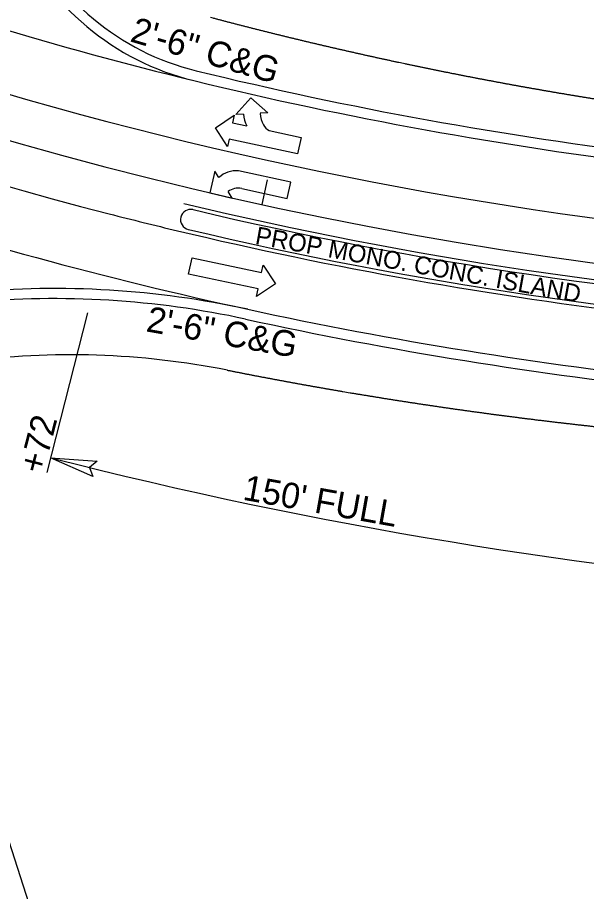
# Model space of a CAD drawing. Extents: x 1616561 to 1622460, y 896726 to 899651.
# Drawn here: x 1619580.2 to 1619692.2, y 897924.5 to 898096.6 of the extents above; entities that cross this region are included whole.
import ezdxf

# ---------------------------------------------------------------- set-up
doc = ezdxf.new("R2010")
doc.units = 0
for name, color, linetype in [('Exist Boundary Study Area', 7, 'Continuous'), ('Old_Level_3', 7, 'Continuous'), ('Prop Dimension', 7, 'Continuous'), ('Prop Guardrail', 7, 'Continuous'), ('Prop Horizontal Alignment Tick Small', 7, 'Continuous'), ('Prop Lane Arrow CELL', 7, 'Continuous'), ('Prop Shade Medium', 7, 'Continuous'), ('Prop Superelevation  Arrow CELL', 7, 'Continuous'), ('Prop Terminator CELL', 7, 'Continuous'), ('Sheet Cutting Line CELL', 7, 'Continuous'), ('Sheet North Arrow CELL', 7, 'Continuous')]:
    doc.layers.add(name, color=color, linetype=linetype)

msp = doc.modelspace()

# ---------------------------------------------------------------- linework, layer by layer
at = {"layer": 'Exist Boundary Study Area'}
for centre, radius, start, end in [((1619614.26, 898056.82), 2, 76.7118, 166.5693), ((1619799.51, 898841.24), 804, 256.71253, 266.38119), ((1619614.26, 898056.82), 2, 166.5693, 256.7115), ((1619799.51, 898841.24), 808, 256.71253, 266.33407)]:
    msp.add_arc(centre, radius, start, end, dxfattribs=at)
at = {"layer": 'Old_Level_3'}
for radius, start, end in [(808.75, 229.34838, 255.58792), (779.25, 244.13867, 256.29422), (791.25, 245.11013, 270), (820.75, 245.81358, 257.75937), (803.25, 256.56929, 266.38119), (808.75, 255.58792, 256.56929), (808.75, 256.56929, 270)]:
    msp.add_arc((1619799.51, 898841.24), radius, start, end, dxfattribs=at)
at = {"layer": 'Prop Dimension'}
msp.add_line((1619593.97, 898038.46), (1619585.91, 898007.01), dxfattribs=at)
msp.add_arc((1619814.99, 898901.46), 920.33, 255.63483, 265.65625, dxfattribs=at)
at = {"layer": 'Prop Guardrail'}
msp.add_arc((1619590.52, 897870.95), 159.23, 78.786, 97.4583, dxfattribs=at)
for points in [[(1619656.5, 898087.47), (1619655.24, 898087.74), (1619654.6, 898087.88), (1619653.97, 898088.01), (1619653.34, 898088.15), (1619652.7, 898088.29), (1619652.07, 898088.42), (1619651.44, 898088.56), (1619650.8, 898088.7), (1619650.17, 898088.84), (1619649.54, 898088.98), (1619648.9, 898089.12), (1619648.27, 898089.26), (1619647.64, 898089.4), (1619647.01, 898089.54), (1619646.37, 898089.69), (1619645.74, 898089.83), (1619645.11, 898089.97), (1619644.48, 898090.12), (1619643.85, 898090.26), (1619643.22, 898090.41), (1619642.58, 898090.55), (1619641.95, 898090.7), (1619641.32, 898090.84), (1619640.69, 898090.99), (1619640.06, 898091.14), (1619639.43, 898091.29), (1619638.8, 898091.44), (1619638.17, 898091.58), (1619637.54, 898091.73), (1619636.91, 898091.88), (1619636.28, 898092.04), (1619635.65, 898092.19), (1619635.02, 898092.34), (1619634.39, 898092.49), (1619633.76, 898092.64), (1619633.13, 898092.8), (1619632.5, 898092.95), (1619631.87, 898093.11), (1619631.24, 898093.26), (1619630.62, 898093.42), (1619629.99, 898093.57), (1619629.36, 898093.73), (1619628.73, 898093.89), (1619628.1, 898094.04), (1619627.47, 898094.2), (1619626.85, 898094.36), (1619626.22, 898094.52), (1619625.59, 898094.68), (1619624.96, 898094.84), (1619624.34, 898095), (1619623.71, 898095.16), (1619623.08, 898095.32), (1619622.46, 898095.49), (1619621.83, 898095.65), (1619621.2, 898095.81), (1619620.58, 898095.98), (1619619.95, 898096.14), (1619619.32, 898096.31), (1619618.7, 898096.47), (1619618.14, 898096.62)], [(1619703.74, 898079.02), (1619702.45, 898079.21), (1619701.81, 898079.31), (1619701.17, 898079.4), (1619700.53, 898079.5), (1619699.89, 898079.6), (1619699.25, 898079.69), (1619698.6, 898079.79), (1619697.96, 898079.89), (1619697.32, 898079.99), (1619696.68, 898080.09), (1619696.04, 898080.19), (1619695.4, 898080.29), (1619694.76, 898080.39), (1619694.12, 898080.5), (1619693.48, 898080.6), (1619692.84, 898080.7), (1619692.2, 898080.81), (1619691.56, 898080.91), (1619690.92, 898081.01), (1619690.28, 898081.12), (1619689.64, 898081.23), (1619689, 898081.33), (1619688.36, 898081.44), (1619687.72, 898081.55), (1619687.08, 898081.65), (1619686.44, 898081.76), (1619685.8, 898081.87), (1619685.16, 898081.98), (1619684.52, 898082.09), (1619683.88, 898082.2), (1619683.24, 898082.31), (1619682.6, 898082.43), (1619681.96, 898082.54), (1619681.32, 898082.65), (1619680.69, 898082.76), (1619680.05, 898082.88), (1619679.41, 898082.99), (1619678.77, 898083.11), (1619678.13, 898083.22), (1619677.49, 898083.34), (1619676.86, 898083.46), (1619676.22, 898083.57), (1619675.58, 898083.69), (1619674.94, 898083.81), (1619674.31, 898083.93), (1619673.67, 898084.05), (1619673.03, 898084.17), (1619672.39, 898084.29), (1619671.76, 898084.41), (1619671.12, 898084.53), (1619670.48, 898084.65), (1619669.85, 898084.78), (1619669.21, 898084.9), (1619668.57, 898085.02), (1619667.94, 898085.15), (1619667.3, 898085.27), (1619666.67, 898085.4), (1619666.03, 898085.52), (1619665.39, 898085.65), (1619664.76, 898085.78), (1619664.12, 898085.9), (1619663.49, 898086.03), (1619662.85, 898086.16), (1619662.22, 898086.29), (1619661.58, 898086.42), (1619660.95, 898086.55), (1619660.31, 898086.68), (1619659.68, 898086.81), (1619659.04, 898086.94), (1619658.41, 898087.07), (1619657.77, 898087.21), (1619657.14, 898087.34), (1619656.5, 898087.47)], [(1619621.48, 898027.14), (1619622.1, 898027.02), (1619622.41, 898026.96), (1619622.71, 898026.9), (1619623.02, 898026.84), (1619623.33, 898026.78), (1619623.63, 898026.72), (1619623.94, 898026.66), (1619624.25, 898026.6), (1619624.56, 898026.54), (1619624.86, 898026.48), (1619625.17, 898026.42), (1619625.48, 898026.36), (1619625.78, 898026.3), (1619626.09, 898026.24), (1619626.4, 898026.18), (1619626.71, 898026.12), (1619627.01, 898026.06), (1619627.32, 898026), (1619627.63, 898025.94), (1619627.94, 898025.89), (1619628.24, 898025.83), (1619628.55, 898025.77), (1619628.86, 898025.71), (1619629.17, 898025.65), (1619629.47, 898025.59), (1619629.78, 898025.54), (1619630.09, 898025.48), (1619630.4, 898025.42), (1619630.71, 898025.36), (1619631.01, 898025.31), (1619631.32, 898025.25), (1619631.63, 898025.19), (1619631.94, 898025.13), (1619632.24, 898025.08), (1619632.55, 898025.02), (1619632.86, 898024.96), (1619633.17, 898024.91), (1619633.48, 898024.85), (1619633.78, 898024.79), (1619634.09, 898024.74), (1619634.4, 898024.68), (1619634.71, 898024.62), (1619635.01, 898024.57), (1619635.32, 898024.51), (1619635.63, 898024.46), (1619635.94, 898024.4), (1619636.25, 898024.35), (1619636.55, 898024.29), (1619636.86, 898024.24), (1619637.17, 898024.18), (1619637.48, 898024.13), (1619637.79, 898024.07), (1619638.09, 898024.02), (1619638.4, 898023.96), (1619638.71, 898023.91), (1619639.02, 898023.85), (1619639.33, 898023.8), (1619639.64, 898023.74), (1619639.94, 898023.69), (1619640.25, 898023.64), (1619640.56, 898023.58), (1619640.87, 898023.53), (1619641.18, 898023.47), (1619641.49, 898023.42), (1619641.79, 898023.37), (1619642.1, 898023.31), (1619642.41, 898023.26), (1619642.72, 898023.21), (1619643.03, 898023.15), (1619643.34, 898023.1), (1619643.64, 898023.05), (1619643.95, 898023), (1619644.26, 898022.94)], [(1619644.26, 898022.94), (1619645.65, 898022.71), (1619646.34, 898022.59), (1619647.04, 898022.48), (1619647.73, 898022.36), (1619648.42, 898022.25), (1619649.12, 898022.13), (1619649.81, 898022.02), (1619650.51, 898021.91), (1619651.2, 898021.8), (1619651.9, 898021.68), (1619652.59, 898021.57), (1619653.29, 898021.46), (1619653.98, 898021.35), (1619654.68, 898021.24), (1619655.37, 898021.13), (1619656.07, 898021.03), (1619656.76, 898020.92), (1619657.46, 898020.81), (1619658.15, 898020.71), (1619658.85, 898020.6), (1619659.54, 898020.49), (1619660.24, 898020.39), (1619660.93, 898020.29), (1619661.63, 898020.18), (1619662.32, 898020.08), (1619663.02, 898019.98), (1619663.72, 898019.88), (1619664.41, 898019.77), (1619665.11, 898019.67), (1619665.8, 898019.57), (1619666.5, 898019.47), (1619667.2, 898019.38), (1619667.89, 898019.28), (1619668.59, 898019.18), (1619669.29, 898019.08), (1619669.98, 898018.99), (1619670.68, 898018.89), (1619671.38, 898018.8), (1619672.07, 898018.7), (1619672.77, 898018.61), (1619673.47, 898018.51), (1619674.16, 898018.42), (1619674.86, 898018.33), (1619675.56, 898018.24), (1619676.25, 898018.15), (1619676.95, 898018.06), (1619677.65, 898017.97), (1619678.35, 898017.88), (1619679.04, 898017.79), (1619679.74, 898017.7), (1619680.44, 898017.61), (1619681.14, 898017.53), (1619681.83, 898017.44), (1619682.53, 898017.35), (1619683.23, 898017.27), (1619683.93, 898017.18), (1619684.63, 898017.1), (1619685.32, 898017.02), (1619686.02, 898016.93), (1619686.72, 898016.85), (1619687.42, 898016.77), (1619688.12, 898016.69), (1619688.81, 898016.61), (1619689.51, 898016.53), (1619690.21, 898016.45), (1619690.91, 898016.37), (1619691.61, 898016.29), (1619692.31, 898016.22), (1619693, 898016.14), (1619693.7, 898016.06), (1619694.4, 898015.99), (1619695.1, 898015.91), (1619695.8, 898015.84)]]:
    msp.add_spline(points, degree=3, dxfattribs=at)
at = {"layer": 'Prop Horizontal Alignment Tick Small'}
for centre, radius, start, end in [((1619627.2, 898134.7), 50, 151.351, 256.2942), ((1619799.51, 898841.24), 777.25, 256.29422, 270), ((1619587.34, 897863.24), 178, 77.7594, 95.2664), ((1619799.51, 898841.24), 822.75, 257.75937, 270)]:
    msp.add_arc(centre, radius, start, end, dxfattribs=at)
at = {"layer": 'Prop Lane Arrow CELL'}
for p, q in [((1619623.17, 898077.48), (1619626.12, 898080.79)), ((1619626.12, 898080.79), (1619629.43, 898077.84)), ((1619629.43, 898077.84), (1619627.98, 898077.74)), ((1619619.15, 898074.91), (1619622.83, 898077.35)), ((1619622.83, 898077.35), (1619622.52, 898075.88)), ((1619624.67, 898077.57), (1619623.17, 898077.48)), ((1619621.52, 898071.19), (1619619.15, 898074.91)), ((1619622.52, 898075.88), (1619625.31, 898075.29)), ((1619629.71, 898074.35), (1619636.02, 898073.01)), ((1619621.83, 898072.65), (1619621.52, 898071.19)), ((1619635.33, 898069.78), (1619621.83, 898072.65)), ((1619636.02, 898073.01), (1619635.33, 898069.78)), ((1619619.03, 898066.35), (1619618.04, 898062.06)), ((1619619.83, 898065.1), (1619619.03, 898066.35)), ((1619633.96, 898064.17), (1619623.65, 898066.42)), ((1619633.26, 898060.95), (1619633.96, 898064.17)), ((1619622.43, 898061.06), (1619621.63, 898062.31)), ((1619624.32, 898062.9), (1619633.26, 898060.95)), ((1619618.04, 898062.06), (1619622.43, 898061.06)), ((1619613.84, 898046.07), (1619614.53, 898049.29)), ((1619614.53, 898049.29), (1619628.22, 898046.38)), ((1619628.22, 898046.38), (1619628.53, 898047.85)), ((1619628.53, 898047.85), (1619630.97, 898044.16)), ((1619627.53, 898043.15), (1619613.84, 898046.07)), ((1619630.97, 898044.16), (1619627.22, 898041.69)), ((1619627.22, 898041.69), (1619627.53, 898043.15))]:
    msp.add_line(p, q, dxfattribs=at)
for centre, radius, start, end in [((1619632.41, 898077.71), 4.43, 179.6953, 210.5488), ((1619629.12, 898077.54), 4.43, 179.5765, 210.4551), ((1619630.84, 898076.61), 2.52, 207.0587, 243.3707), ((1619623.32, 898061.19), 5.25, 86.3809, 131.6926), ((1619623.61, 898059.72), 3.28, 77.7048, 127.363)]:
    msp.add_arc(centre, radius, start, end, dxfattribs=at)
at = {"layer": 'Prop Shade Medium'}
msp.add_line((1619612.32, 898057.28), (1619612.32, 898057.28), dxfattribs=at)
for centre, radius, start, end in [((1619614.26, 898056.82), 2, 76.7118, 166.5693), ((1619799.51, 898841.24), 804, 256.71253, 266.38119), ((1619614.26, 898056.82), 2, 166.5693, 256.7115), ((1619799.51, 898841.24), 808, 256.71253, 266.33392)]:
    msp.add_arc(centre, radius, start, end, dxfattribs=at)
at = {"layer": 'Prop Superelevation  Arrow CELL'}
msp.add_line((1619628.32, 898059.77), (1619629.39, 898064.66), dxfattribs=at)
at = {"layer": 'Prop Terminator CELL'}
msp.add_lwpolyline([(1619594.99, 898006.18), (1619586.66, 898009.91), (1619595.82, 898009.22), (1619594.31, 898007.95)], close=True, dxfattribs=at)
for centre, radius, start, end in [((1619627.2, 898134.7), 52, 151.351, 256.2942), ((1619799.51, 898841.24), 779.25, 256.29422, 270), ((1619587.34, 897863.24), 180, 77.7594, 95.2664), ((1619799.51, 898841.24), 820.75, 257.75937, 270)]:
    msp.add_arc(centre, radius, start, end, dxfattribs=at)
at = {"layer": 'Sheet Cutting Line CELL'}
msp.add_arc((1619799.51, 898841.24), 800, 229.34838, 270, dxfattribs=at)
at = {"layer": 'Sheet North Arrow CELL'}
msp.add_line((1619528.74, 898088.46), (1619598.19, 897873.05), dxfattribs=at)

# ---------------------------------------------------------------- texts
at = {"layer": 'Prop Dimension'}
for s, height, rotation, p in [('2\'-6" C&G', 5.044, 343.6844, (1619602.12, 898091.95)), ('PROP MONO. CONC. ISLAND', 3.5, 349.7101, (1619626.8, 898052.03)), ('2\'-6" C&G', 5.044, 349.9517, (1619605.31, 898034.81)), ('+72', 5, 75.5879, (1619585.21, 898006.53)), ("150' FULL", 5, 349.8638, (1619624.36, 898001.65))]:
    msp.add_text(s, height=height, rotation=rotation, dxfattribs=at).set_placement(p)

doc.saveas('drawing.dxf')
